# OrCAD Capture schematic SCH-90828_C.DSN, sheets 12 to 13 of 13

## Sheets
12 12 HEADERS: size C; note: SCH-90828 PDF: SPF-90828
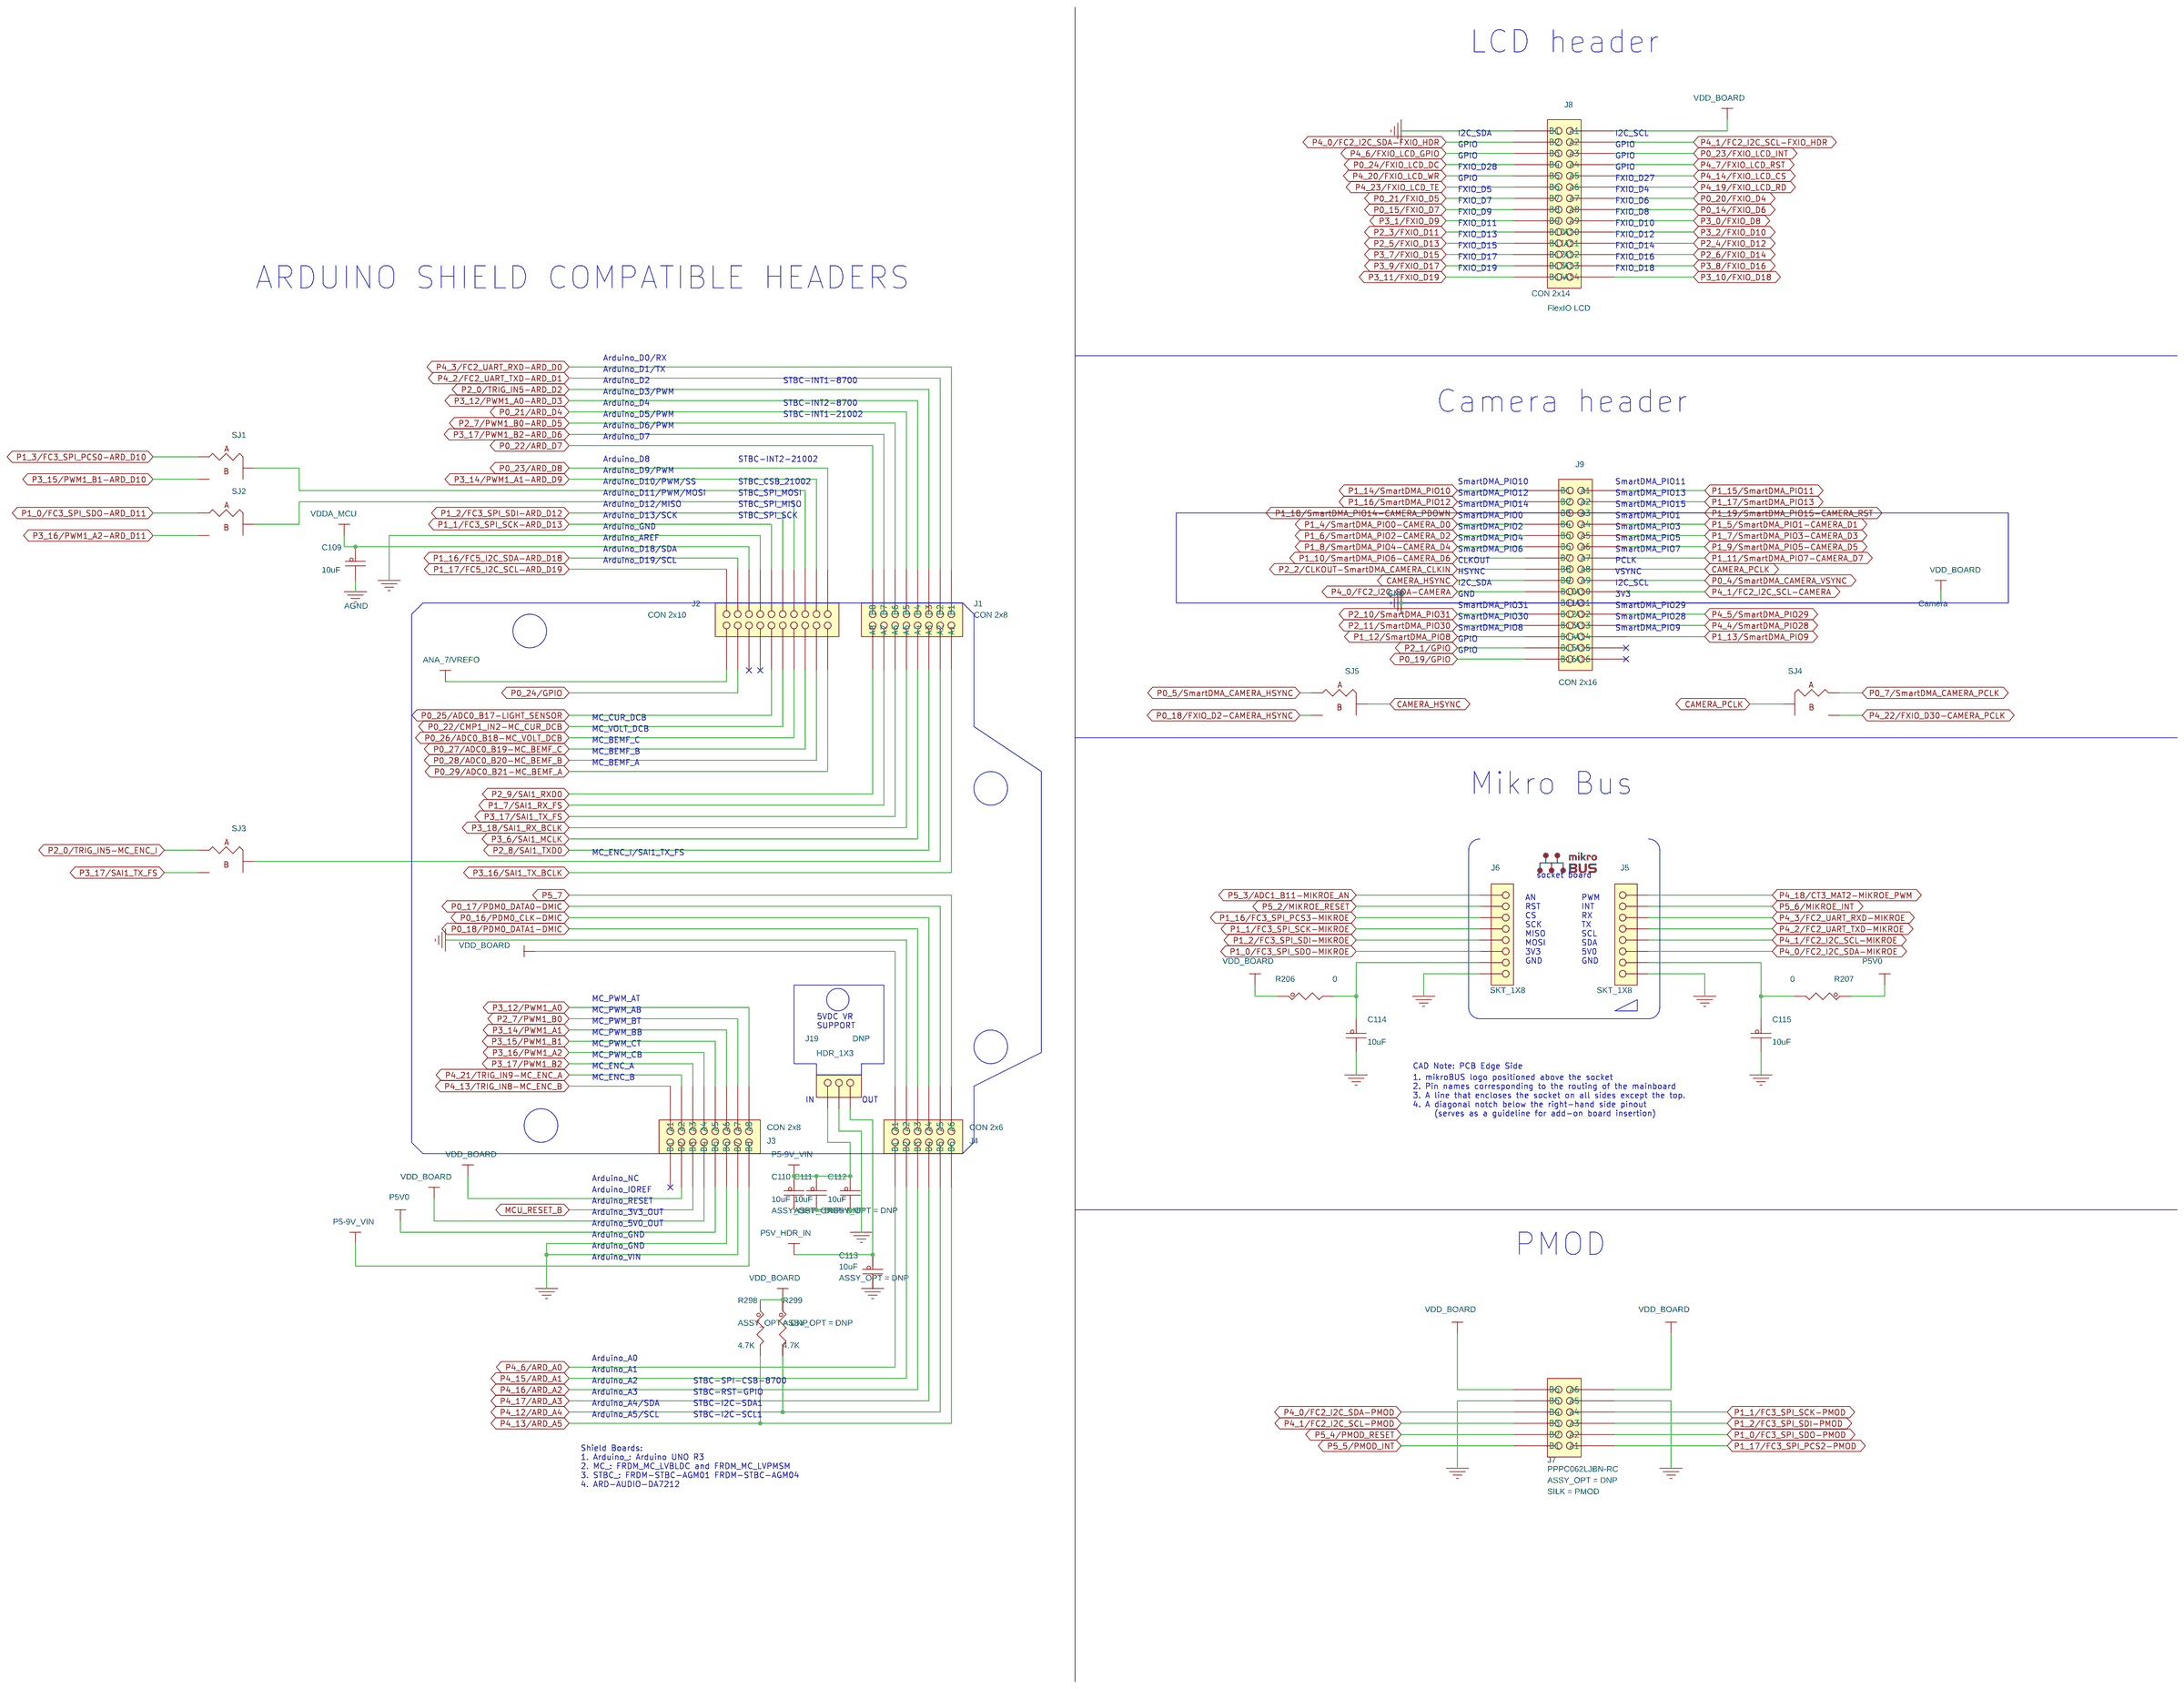
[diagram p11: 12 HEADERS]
13 13 APPENDIX JUMPER/DNP: note: SCH-90828 PDF: SPF-90828
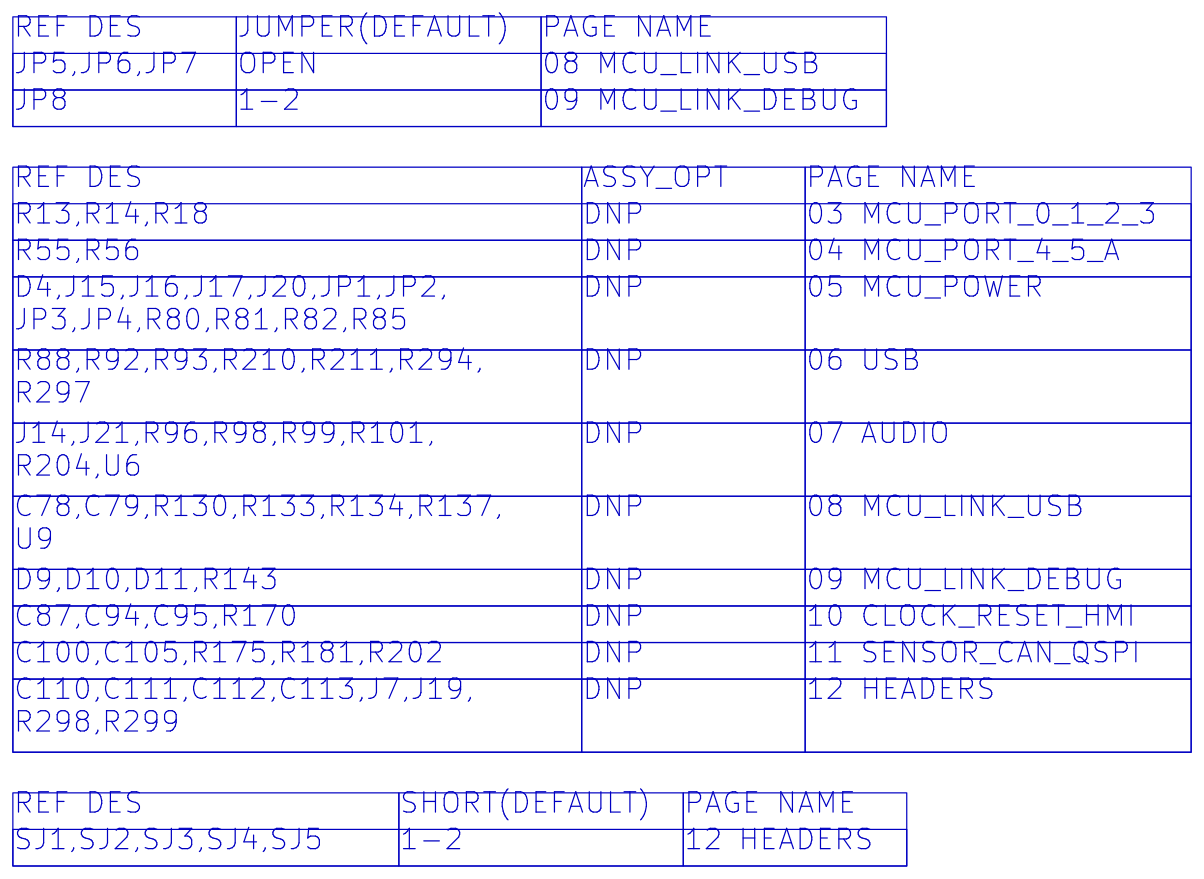
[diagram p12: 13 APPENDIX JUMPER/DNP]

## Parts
C109  10uF  [CC0603_OV]
C110  10uF  [CC0603_OV]
C111  10uF  [CC0603_OV]
C112  10uF  [CC0603_OV]
C113  10uF  [CC0603_OV]
C114  10uF  [CC0603_OV]
C115  10uF  [CC0603_OV]
J1  CON 2x8  [con_2x8_skt_100_th]
J2  CON 2x10  [con_skt2x10_th]
J3  CON 2x8  [con_2x8_skt_100_th]
J4  CON 2x6  [con_skt2x6_th_126l]
J5  SKT_1X8  [con_1x8_skt_2p54_th_126l]
J6  SKT_1X8  [con_1x8_skt_2p54_th_126l]
J7  PPPC062LJBN-RC  [skt2x6_100_th_ra]
J8  CON 2x14  [con_skt2x14_th_126l]
J9  CON 2x16  [con_skt_32f_100_th]
J19  HDR_1X3  [HDR103]
R206  0  [RC0603_OV]
R207  0  [RC0603_OV]
R298  4.7K  [RC0402_25]
R299  4.7K  [RC0402_25]
SJ1  3 PIN 0402 JUMPER  [3pin_0402x2_a]
SJ2  3 PIN 0402 JUMPER  [3pin_0402x2_a]
SJ3  3 PIN 0402 JUMPER  [3pin_0402x2_a]
SJ4  3 PIN 0402 JUMPER  [3pin_0402x2_a]
SJ5  3 PIN 0402 JUMPER  [3pin_0402x2_a]

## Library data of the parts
C109 C114 C115 = CAP_NP: CAP CER 10uF 25V 10% X5R 0603; 3D_Mechanical_Footprint_File: http://fcl.am.freescale.net/ALLEGRO/step/cc0603_ov.STEP; AGILE_PN: 150-79569; CAD_APPROVED: Yes; HEIGHT: 1; MFG_NAME01: SANYEAR; MFG_PN01: C0603X5R106K250NT; Package Size: 0603 [1608 Metric]; Package Type: SMD/SMT; ROHS: Yes; Rated Voltage: 25V; Tolerance: 10%
C110-C113 = CAP_NP: CAP CER 10uF 25V 10% X5R 0603; 3D_Mechanical_Footprint_File: http://fcl.am.freescale.net/ALLEGRO/step/cc0603_ov.STEP; AGILE_PN: 150-79569; ASSY_OPT: DNP; CAD_APPROVED: Yes; HEIGHT: 1; MFG_NAME01: SANYEAR; MFG_PN01: C0603X5R106K250NT; Package Size: 0603 [1608 Metric]; Package Type: SMD/SMT; ROHS: Yes; Rated Voltage: 25V; Tolerance: 10%
J1 J3 = CONN_HDR_8X2: CON 2X8 SKT SHRD TH 100MIL CTR 345H AU 126L; 3D_Mechanical_Footprint_File: http://fcl.am.freescale.net/ALLEGRO/step/con_2x8_skt_100_th.STEP; AGILE_PN: 210-81775; CAD_APPROVED: Yes; HEIGHT: 8.75; MFG_NAME01: ANYTRONIC CORPORATION LIMITED; MFG_PN01: 08010S31611-29RF; ROHS: Yes; Temp Range: -40 to +105C
J2 = CONN_HDR_10X2: CON 2X10 SKT SHRD TH 100MIL CTR 345H AU 126L; 3D_Mechanical_Footprint_File: http://fcl.am.freescale.net/ALLEGRO/step/con_skt2x10_th.STEP; AGILE_PN: 210-81776; CAD_APPROVED: Yes; HEIGHT: 8.75; MFG_NAME01: ANYTRONIC CORPORATION LIMITED; MFG_PN01: 08010S32011-29RF; ROHS: Yes; Temp Range: -40 to +105C
J4 = CONN_HDR_6X2: CON 2X6 SKT SHRD TH 100MIL CTR 345H AU 126L; 3D_Mechanical_Footprint_File: http://fcl.am.freescale.net/ALLEGRO/step/con_skt2x6_th_126l.STEP; AGILE_PN: 210-81774; CAD_APPROVED: Yes; FPLIST: con_skt2x6_th_126l,con_skt2x6_th; HEIGHT: 8.75; MFG_NAME01: ANYTRONIC CORPORATION LIMITED; MFG_PN01: 08010S31211-29RF; ROHS: Yes; Temp Range: -40 to +105C
J5 J6 = CONN_HDR_8X1: CON 1X8 SKT TH 100MIL SP 344H AU 118L; 3D_Mechanical_Footprint_File: http://fcl.am.freescale.net/ALLEGRO/step/con_1x8_skt_2p54_th_126l.STEP; AGILE_PN: 210-81617; CAD_APPROVED: Yes; FPLIST: con_1x8_skt_2p54_th_126l,con_1x8_skt_2p54_th; HEIGHT: 8.75; MFG_NAME01: ANYTRONIC CORPORATION LIMITED; MFG_PN01: 08001S3 0811-29RF; ROHS: Yes; Temp Range: -40°C to +105°C
J7 = CONN_HDR_6X2: CON 2X6 SKT RA TH 100MIL CTR 206H AU 124L; 3D_Mechanical_Footprint_File: http://fcl.am.freescale.net/ALLEGRO/step/skt2x6_100_th_ra.step; AGILE_PN: 210-80998; ASSY_OPT: DNP; CAD_APPROVED: Yes; HEIGHT: 5.28; MFG_NAME01: SULLINS ELECTRONICS CORP; ROHS: Yes; SILK: PMOD
J8 = CONN_HDR_14X2: CON 2X14 SKT SHRD TH 100MIL CTR 345H AU 126L; 3D_Mechanical_Footprint_File: http://fcl.am.freescale.net/ALLEGRO/step/con_skt2x14_th_126l.STEP; AGILE_PN: 210-83442; CAD_APPROVED: Yes; HEIGHT: 8.75; MFG_NAME01: ANYTRONIC CORPORATION LIMITED; MFG_PN01: 08010S32811-29RF; ROHS: Yes; SILK: FlexIO LCD; Temp Range: -40 to +105C
J9 = CONN_HDR_16X2: CON 2X16 SKT SHRD TH 100MIL CTR 345H AU 126L; AGILE_PN: 210-83440; CAD_APPROVED: Yes; HEIGHT: 8.75; MFG_NAME01: ANYTRONIC CORPORATION LIMITED; MFG_PN01: 08010S33211-29RF; ROHS: Yes; SILK: Camera; Temp Range: -40 to +105C
J19 = CONN_HDR_3X1: HDR 1X3 TH 100MIL SP 330H AU 98L; 3D_Mechanical_Footprint_File: http://fcl.am.freescale.net/ALLEGRO/step/hdr103_330h.STEP; AGILE_PN: 210-75442; ASSY_OPT: DNP; CAD_APPROVED: Yes; HEIGHT: 8.59; MFG_NAME01: SAMTEC; MFG_PN01: HTSW-103-07-S-S; PRIORITY_PN: 028-00700; Package Type: HEADER; ROHS: Yes; Temp Range: -55°C to +125°C
R206 R207 = RES: RES MF ZERO OHM 1/10W -- 0603; AGILE_PN: 470-80866; CAD_APPROVED: Yes; FPLIST: RC0603_OV,RC0603,R603-X2,r603-x2_b,0603_CC,IND_0603HP_NSP,CC0603_OV_NSP; HEIGHT: 0.6; MFG_NAME01: YAGEO AMERICA; MFG_PN01: RC0603FR-070RL; ROHS: Yes; Temp Range: –55 °C to +155 °C
R298 R299 = RES: RES MF 4.7K OHM 1/16W 1% 0402; AGILE_PN: 470-80911; ASSY_OPT: DNP; CAD_APPROVED: Yes; FPLIST: RC0402_25,RC0402_HD,0402_CC; HEIGHT: 0.4; MFG_NAME01: YAGEO; MFG_PN01: RC0402FR-074K7L; ROHS: Yes; Tolerance: 1%
SJ1-SJ5 = RES_3PIN_C: SOLDER BLOB JUMPER 3PIN 1-2 SHORT 0402 - NO PART TO ORDER; AGILE_PN: 470-83592; CAD_APPROVED: Yes; HEIGHT: 0.1016; MFG_NAME01: NA; ROHS: Yes; SHORT(DEFAULT): 1-2

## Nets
AGND: C109.2 ; also on sheet 5
GND: C110.2 C111.2 C112.2 C113.2 C114.2 C115.2 J2.14 J3.12(B6) J3.14(B7) J4.3(A2) J5.8 J6.8 J7.9(A5) J7.10(B5) J8.2(B1) J9.22(B11) J19.2 ; also on sheet 5 6 7 8 9 10 11
P5V0: J3.10(B5) R207.1 ; also on sheet 5 6 11
P5V_HDR_IN: C113.1 J19.3 ; also on sheet 5
VDD_BOARD: J3.4(B2) J3.8(B4) J4.1(A1) J7.11(A6) J7.12(B6) J8.1(A1) J9.21(A11) R206.1 R298.1 R299.1 ; also on sheet 3 4 5 6 7 8 9 10 11
VDDA_MCU: C109.1 J2.16 ; also on sheet 5
ANA_7/VREFO: J2.19 ; also on sheet 5
CAMERA_HSYNC: J9.18(B9) SJ5.2
CAMERA_PCLK: J9.15(A8) SJ4.2
MCU_RESET_B: J3.6(B3) ; also on sheet 4 9 10
P0_4/SmartDMA_CAMERA_VSYNC: J9.17(A9) ; also on sheet 3
P0_5/SmartDMA_CAMERA_HSYNC: SJ5.1 ; also on sheet 3
P0_7/SmartDMA_CAMERA_PCLK: SJ4.1 ; also on sheet 3
P0_14/FXIO_D6: J8.15(A8) ; also on sheet 3
P0_15/FXIO_D7: J8.16(B8) ; also on sheet 3
P0_16/PDM0_CLK-DMIC: J4.7(A4) ; also on sheet 3 7
P0_17/PDM0_DATA0-DMIC: J4.9(A5) ; also on sheet 3 7
P0_18: J4.5(A3) SJ5.3 ; also on sheet 3
P0_19/GPIO: J9.32(B16) ; also on sheet 3
P0_20: J8.13(A7) ; also on sheet 3
P0_21: J1.10(B5) J8.14(B7) ; also on sheet 3
P0_22: J1.16(B8) J2.9 ; also on sheet 3
P0_23: J2.2 J8.5(A3) ; also on sheet 3
P0_24: J2.17 J8.8(B4) ; also on sheet 3
P0_25/ADC0_B17-LIGHT_SENSOR: J2.11 ; also on sheet 3 11
P0_26/ADC0_B18-MC_VOLT_DCB: J2.7 ; also on sheet 3
P0_27/ADC0_B19-MC_BEMF_C: J2.5 ; also on sheet 3
P0_28/ADC0_B20-MC_BEMF_B: J2.3 ; also on sheet 3
P0_29/ADC0_B21-MC_BEMF_A: J2.1 ; also on sheet 3
P1_0: J6.6 J7.3(A2) ; also on sheet 3 9
P1_0/FC3_SPI_SDO-ARD_D11: SJ2.1 ; also on sheet 3
P1_1: J2.12 J6.4 J7.7(A4) ; also on sheet 3 9
P1_2: J2.10 J6.5 J7.5(A3) ; also on sheet 3 9
P1_3: SJ1.1 ; also on sheet 3 9
P1_4/SmartDMA_PIO0-CAMERA_D0: J9.8(B4) ; also on sheet 3
P1_5/SmartDMA_PIO1-CAMERA_D1: J9.7(A4) ; also on sheet 3
P1_6/SmartDMA_PIO2-CAMERA_D2: J9.10(B5) ; also on sheet 3
P1_7: J9.9(A5) ; also on sheet 3
P1_7/SAI1_RX_FS: J1.13(A7) ; also on sheet 3
P1_8: J9.12(B6) ; also on sheet 3 4
P1_9: J9.11(A6) ; also on sheet 3 4
P1_10/SmartDMA_PIO6-CAMERA_D6: J9.14(B7) ; also on sheet 3
P1_11/SmartDMA_PIO7-CAMERA_D7: J9.13(A7) ; also on sheet 3
P1_12/SmartDMA_PIO8: J9.28(B14) ; also on sheet 3
P1_13/SmartDMA_PIO9: J9.27(A14) ; also on sheet 3
P1_14/SmartDMA_PIO10: J9.2(B1) ; also on sheet 3
P1_15/SmartDMA_PIO11: J9.1(A1) ; also on sheet 3
P1_16: J6.3 J9.4(B2) ; also on sheet 3
P1_16/FC5_I2C_SDA-ARD_D18: J2.18 ; also on sheet 3
P1_17: J7.1(A1) J9.3(A2) ; also on sheet 3
P1_17/FC5_I2C_SCL-ARD_D19: J2.20 ; also on sheet 3
P1_18/SmartDMA_PIO14-CAMERA_PDOWN: J9.6(B3) ; also on sheet 3
P1_19/SmartDMA_PIO15-CAMERA_RST: J9.5(A3) ; also on sheet 3
P2_0: J1.6(B3) SJ3.1 ; also on sheet 3
P2_1/GPIO: J9.30(B15) ; also on sheet 3
P2_2/CLKOUT-SmartDMA_CAMERA_CLKIN: J9.16(B8) ; also on sheet 3
P2_3/FXIO_D11: J8.20(B10) ; also on sheet 3
P2_4/FXIO_D12: J8.21(A11) ; also on sheet 3
P2_5/FXIO_D13: J8.22(B11) ; also on sheet 3
P2_6/FXIO_D14: J8.23(A12) ; also on sheet 3
P2_7: J1.12(B6) J3.13(A7) ; also on sheet 3
P2_8/SAI1_TXD0: J1.5(A3) ; also on sheet 3 7
P2_9/SAI1_RXD0: J1.15(A8) ; also on sheet 3 7
P2_10/SmartDMA_PIO31: J9.24(B12) ; also on sheet 3
P2_11/SmartDMA_PIO30: J9.26(B13) ; also on sheet 3
P3_0/FXIO_D8: J8.17(A9) ; also on sheet 3
P3_1/FXIO_D9: J8.18(B9) ; also on sheet 3
P3_2/FXIO_D10: J8.19(A10) ; also on sheet 3
P3_6/SAI1_MCLK: J1.7(A4) ; also on sheet 3 7
P3_7/FXIO_D15: J8.24(B12) ; also on sheet 3
P3_8/FXIO_D16: J8.25(A13) ; also on sheet 3
P3_9/FXIO_D17: J8.26(B13) ; also on sheet 3
P3_10/FXIO_D18: J8.27(A14) ; also on sheet 3
P3_11/FXIO_D19: J8.28(B14) ; also on sheet 3
P3_12/PWM1_A0: J1.8(B4) J3.15(A8) ; also on sheet 3
P3_14: J2.4 J3.11(A6) ; also on sheet 3
P3_15: J3.9(A5) SJ1.3 ; also on sheet 3
P3_16: J1.1(A1) J3.7(A4) SJ2.3 ; also on sheet 3 7
P3_17: J1.11(A6) J1.14(B7) J3.5(A3) SJ3.3 ; also on sheet 3 7
P3_18/SAI1_RX_BCLK: J1.9(A5) ; also on sheet 3
P4_0: J5.6 J7.8(B4) J8.4(B2) J9.20(B10) ; also on sheet 4 6 7
P4_1: J5.5 J7.6(B3) J8.3(A2) J9.19(A10) ; also on sheet 4 6 7
P4_2: J1.4(B2) J5.4 ; also on sheet 4
P4_3: J1.2(B1) J5.3 ; also on sheet 4
P4_4/SmartDMA_PIO28: J9.25(A13) ; also on sheet 4
P4_5/SmartDMA_PIO29: J9.23(A12) ; also on sheet 4
P4_6: J4.2(B1) J8.6(B3) ; also on sheet 4
P4_7/FXIO_LCD_RST: J8.7(A4) ; also on sheet 4
P4_12/ARD_A4: J4.10(B5) R299.2 ; also on sheet 4
P4_13: J4.12(B6) R298.2 ; also on sheet 4
P4_13/TRIG_IN8-MC_ENC_B: J3.1(A1) ; also on sheet 4
P4_14/FXIO_LCD_CS: J8.9(A5) ; also on sheet 4
P4_15: J4.4(B2) ; also on sheet 4
P4_16: J4.6(B3) ; also on sheet 4 6
P4_17: J4.8(B4) ; also on sheet 4 6 10
P4_18: J5.1 ; also on sheet 4 10
P4_19: J8.11(A6) ; also on sheet 4 10
P4_20/FXIO_LCD_WR: J8.10(B5) ; also on sheet 4
P4_21/TRIG_IN9-MC_ENC_A: J3.3(A2) ; also on sheet 4
P4_22/FXIO_D30-CAMERA_PCLK: SJ4.3 ; also on sheet 4
P4_23/FXIO_LCD_TE: J8.12(B6) ; also on sheet 4
P5-9V_VIN: C110.1 C111.1 C112.1 J3.16(B8) J19.1
P5_2/MIKROE_RESET: J6.2 ; also on sheet 4
P5_3/ADC1_B11-MIKROE_AN: J6.1 ; also on sheet 4
P5_4/PMOD_RESET: J7.4(B2) ; also on sheet 4
P5_5/PMOD_INT: J7.2(B1) ; also on sheet 4
P5_6/MIKROE_INT: J5.2 ; also on sheet 4
P5_7: J4.11(A6) ; also on sheet 4 6
N1499275: J2.6 SJ1.2
N1499293: J2.8 SJ2.2
N1499583: J1.3(A2) SJ3.2
N17616471: C114.1 J6.7 R206.2
N17616475: C115.1 J5.7 R207.2

Not connected (* = marked no-connect by the designer): J2 13* 15*; J3 2(B1)*; J9 29(A15)* 31(A16)*

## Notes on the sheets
sheet 12
- LCD header
- I2C_SDA
- I2C_SCL
- GPIO
- GPIO
- GPIO
- GPIO
- FXIO_D28
- GPIO
- FXIO_D5
- GPIO
- FXIO_D27
- FXIO_D4
- FXIO_D7
- FXIO_D6
- FXIO_D9
- FXIO_D8
- FXIO_D11
- FXIO_D10
- FXIO_D13
- FXIO_D12
- FXIO_D15
- FXIO_D14
- ARDUINO SHIELD COMPATIBLE HEADERS
- FXIO_D17
- FXIO_D19
- FXIO_D16
- FXIO_D18
- Arduino_D0/RX
- Arduino_D1/TX
- Arduino_D2
- STBC-INT1-8700
- Arduino_D3/PWM
- Camera header
- Arduino_D4
- Arduino_D5/PWM
- STBC-INT1-21002
- STBC-INT2-8700
- Arduino_D6/PWM
- Arduino_D7
- Arduino_D8
- STBC-INT2-21002
- Arduino_D10/PWM/SS
- Arduino_D9/PWM
- STBC_CSB_21002
- SmartDMA_PIO10
- SmartDMA_PIO11
- Arduino_D11/PWM/MOSI
- STBC_SPI_MOSI
- SmartDMA_PIO12
- SmartDMA_PIO13
- Arduino_D12/MISO
- STBC_SPI_MISO
- SmartDMA_PIO14
- SmartDMA_PIO15
- Arduino_D13/SCK
- STBC_SPI_SCK
- SmartDMA_PIO0
- SmartDMA_PIO1
- Arduino_GND
- SmartDMA_PIO2
- SmartDMA_PIO3
- Arduino_AREF
- SmartDMA_PIO4
- SmartDMA_PIO5
- Arduino_D18/SDA
- Arduino_D19/SCL
- CLKOUT
- SmartDMA_PIO6
- PCLK
- SmartDMA_PIO7
- HSYNC
- VSYNC
- I2C_SDA
- I2C_SCL
- GND
- 3V3
- SmartDMA_PIO31
- SmartDMA_PIO29
- SmartDMA_PIO30
- SmartDMA_PIO8
- SmartDMA_PIO28
- SmartDMA_PIO9
- GPIO
- GPIO
- MC_CUR_DCB
- MC_VOLT_DCB
- MC_BEMF_C
- MC_BEMF_B
- MC_BEMF_A
- Mikro Bus
- MC_ENC_I/SAI1_TX_FS
- socket board
- AN
  RST
  CS
  SCK
  MISO
  MOSI
  3V3
  GND
- PWM
  INT
  RX
  TX
  SCL
  SDA
  5V0
  GND
- MC_PWM_AT
- MC_PWM_AB
- MC_PWM_BT
- 5VDC VR
  SUPPORT
- MC_PWM_BB
- MC_PWM_CT
- MC_PWM_CB
- MC_ENC_A
- MC_ENC_B
- 1. mikroBUS logo positioned above the socket
  2. Pin names corresponding to the routing of the mainboard
  3. A line that encloses the socket on all sides except the top.
  4. A diagonal notch below the right-hand side pinout
       (serves as a guideline for add-on board insertion)
- CAD Note: PCB Edge Side
- IN
- OUT
- Arduino_NC
- Arduino_IOREF
- Arduino_RESET
- Arduino_3V3_OUT
- Arduino_5V0_OUT
- Arduino_GND
- PMOD
- Arduino_GND
- Arduino_VIN
- Arduino_A0
- Arduino_A1
- Arduino_A2
- STBC-SPI-CSB-8700
- Arduino_A3
- STBC-RST-GPIO
- Arduino_A4/SDA
- STBC-I2C-SDA1
- Arduino_A5/SCL
- STBC-I2C-SCL1
- Shield Boards:
  1. Arduino_: Arduino UNO R3
  2. MC_: FRDM_MC_LVBLDC and FRDM_MC_LVPMSM
  3. STBC_: FRDM-STBC-AGM01 FRDM-STBC-AGM04
  4. ARD-AUDIO-DA7212
sheet 13
- REF DES
- JUMPER(DEFAULT)
- PAGE NAME
- JP5,JP6,JP7
- OPEN
- 08 MCU_LINK_USB
- JP8
- 1-2
- 09 MCU_LINK_DEBUG
- REF DES
- ASSY_OPT
- PAGE NAME
- R13,R14,R18
- DNP
- 03 MCU_PORT_0_1_2_3
- R55,R56
- DNP
- 04 MCU_PORT_4_5_A
- D4,J15,J16,J17,J20,JP1,JP2,
  JP3,JP4,R80,R81,R82,R85
- DNP
- 05 MCU_POWER
- R88,R92,R93,R210,R211,R294,
  R297
- DNP
- 06 USB
- J14,J21,R96,R98,R99,R101,
  R204,U6
- DNP
- 07 AUDIO
- C78,C79,R130,R133,R134,R137,
  U9
- DNP
- 08 MCU_LINK_USB
- D9,D10,D11,R143
- DNP
- 09 MCU_LINK_DEBUG
- C87,C94,C95,R170
- DNP
- 10 CLOCK_RESET_HMI
- C100,C105,R175,R181,R202
- DNP
- 11 SENSOR_CAN_QSPI
- C110,C111,C112,C113,J7,J19,
  R298,R299
- DNP
- 12 HEADERS
- REF DES
- SHORT(DEFAULT)
- PAGE NAME
- SJ1,SJ2,SJ3,SJ4,SJ5
- 1-2
- 12 HEADERS
